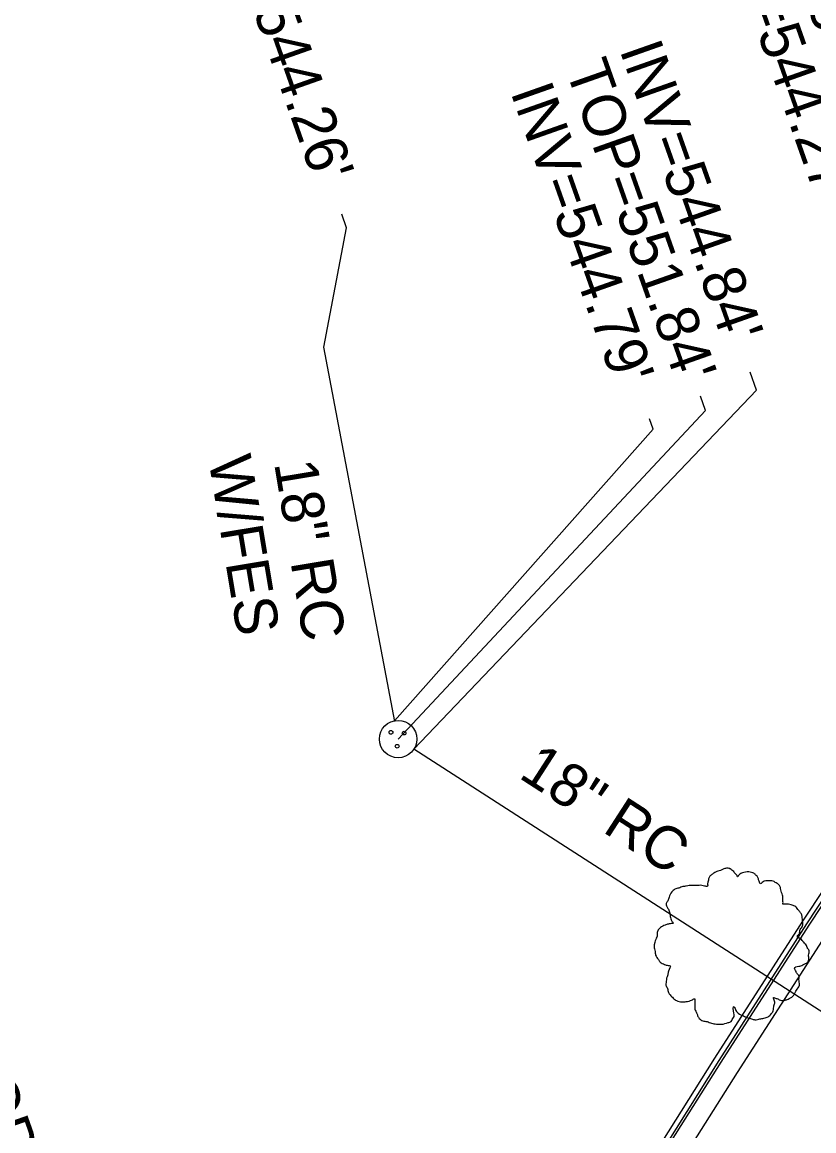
# Model space of a CAD drawing. Extents: x 2004847 to 2009016, y 1134161 to 1140101.
# Drawn here: x 2007863.9 to 2007937.9, y 1139162.8 to 1139266.5 of the extents above; entities that cross this region are included whole.
import ezdxf

# ---------------------------------------------------------------- set-up
doc = ezdxf.new("R2010")
doc.units = 0
for name, color, linetype in [('RD_EX_Curb', 7, 'Continuous'), ('RD_EX_DR_Inlet', 7, 'Continuous'), ('RD_EX_DR_Inlet_txCode', 7, 'Continuous'), ('RD_EX_DR_Pipe', 7, 'Continuous'), ('RD_EX_DR_Pipe_txCode', 7, 'Continuous'), ('RD_EX_Road', 7, 'Continuous'), ('RD_EX_VEG', 7, 'Continuous'), ('RD_Sketch2', 7, 'Continuous')]:
    doc.layers.add(name, color=color, linetype=linetype)

msp = doc.modelspace()

# ---------------------------------------------------------------- linework, layer by layer
at = {"layer": 'RD_EX_Curb'}
for points in [[(2007851.74, 1139039.76), (2007859.24, 1139052.98), (2007866.61, 1139066.11), (2007873.99, 1139079.28), (2007881.46, 1139092.4), (2007889.19, 1139105.44), (2007896.87, 1139118.33), (2007904.72, 1139131.27), (2007912.69, 1139144.1), (2007920.68, 1139156.93), (2007928.66, 1139169.64), (2007936.89, 1139182.44), (2007945.18, 1139194.94), (2007953.65, 1139207.52), (2007962.07, 1139219.98), (2007965.84, 1139225.5)], [(2007852.17, 1139039.53), (2007859.64, 1139052.76), (2007866.98, 1139065.9), (2007874.37, 1139079.07), (2007881.83, 1139092.18), (2007889.55, 1139105.22), (2007897.24, 1139118.11), (2007905.04, 1139131.08), (2007913.02, 1139143.89), (2007921.07, 1139156.68), (2007929.04, 1139169.4), (2007937.26, 1139182.2), (2007945.52, 1139194.72), (2007954.01, 1139207.28), (2007962.42, 1139219.75), (2007966.16, 1139225.27)], [(2007852.4, 1139039.41), (2007859.85, 1139052.64), (2007867.2, 1139065.77), (2007874.59, 1139078.94), (2007882.05, 1139092.06), (2007889.77, 1139105.09), (2007897.44, 1139117.99), (2007905.23, 1139130.96), (2007913.16, 1139143.81), (2007921.23, 1139156.58), (2007929.25, 1139169.27), (2007937.47, 1139182.06), (2007945.72, 1139194.58), (2007954.17, 1139207.17), (2007962.6, 1139219.62), (2007966.32, 1139225.16)]]:
    msp.add_lwpolyline(points, dxfattribs=at)
at = {"layer": 'RD_EX_DR_Inlet'}
for centre, radius in [((2007899.03, 1139199.47), 1.75), ((2007898.36, 1139200.1), 0.175), ((2007899.59, 1139200.03), 0.175), ((2007898.94, 1139198.8), 0.175)]:
    msp.add_circle(centre, radius, dxfattribs=at)
at = {"layer": 'RD_EX_DR_Inlet_txCode'}
for points in [[(2007892.07, 1139236.12), (2007894.21, 1139247.27), (2007893.76, 1139248.55)], [(2007900.5, 1139198.52), (2007932.53, 1139232.1), (2007931.94, 1139233.77)], [(2007899.03, 1139199.47), (2007927.78, 1139230.2), (2007927.3, 1139231.55)], [(2007898.7, 1139201.19), (2007922.88, 1139228.46), (2007922.54, 1139229.42)]]:
    msp.add_lwpolyline(points, dxfattribs=at)
at = {"layer": 'RD_EX_DR_Pipe'}
for p, q in [((2007898.72, 1139201.12), (2007892.07, 1139236.12)), ((2007976.72, 1139149.41), (2007900.5, 1139198.52))]:
    msp.add_line(p, q, dxfattribs=at)
at = {"layer": 'RD_EX_Road'}
msp.add_lwpolyline([(2007854.06, 1139038.51), (2007861.51, 1139051.72), (2007868.85, 1139064.84), (2007876.23, 1139078), (2007883.69, 1139091.1), (2007891.4, 1139104.12), (2007899.06, 1139117.02), (2007906.85, 1139129.97), (2007914.77, 1139142.81), (2007922.77, 1139155.61), (2007930.78, 1139168.29), (2007938.99, 1139181.07), (2007947.3, 1139193.55), (2007955.76, 1139206.1), (2007964.18, 1139218.54), (2007967.91, 1139224.07)], dxfattribs=at)
at = {"layer": 'RD_EX_VEG'}
for points in [[(2007930.04, 1139187.37), (2007929.74, 1139187.39), (2007929.42, 1139187.29), (2007929.17, 1139187.19), (2007928.94, 1139187.12), (2007928.72, 1139187.02), (2007928.42, 1139186.84), (2007928.19, 1139186.64), (2007928.07, 1139186.39), (2007928.02, 1139186.17), (2007927.97, 1139185.89), (2007927.97, 1139185.72), (2007927.84, 1139185.69), (2007927.69, 1139185.72), (2007927.44, 1139185.79), (2007927.19, 1139185.79), (2007926.94, 1139185.79), (2007926.59, 1139185.77), (2007926.25, 1139185.77), (2007925.97, 1139185.72), (2007925.65, 1139185.67), (2007925.27, 1139185.54), (2007924.92, 1139185.42), (2007924.62, 1139185.17), (2007924.37, 1139184.69), (2007924.25, 1139184.34), (2007924.1, 1139184.09), (2007924.25, 1139183.64), (2007924.42, 1139183.29), (2007924.45, 1139183.09), (2007924.52, 1139182.67), (2007924.62, 1139182.44), (2007924.75, 1139182.24), (2007924.67, 1139182.22), (2007924.3, 1139182.17), (2007924, 1139182.07), (2007923.57, 1139181.84), (2007923.35, 1139181.62), (2007923.25, 1139181.29), (2007923.22, 1139180.94), (2007923.12, 1139180.74), (2007923.05, 1139180.47), (2007923.02, 1139180.39), (2007922.97, 1139180.07), (2007923.07, 1139179.62), (2007923.1, 1139179.27), (2007923.22, 1139179.05), (2007923.37, 1139178.87), (2007923.55, 1139178.62), (2007923.95, 1139178.4), (2007924.27, 1139178.3), (2007924.47, 1139178.27), (2007924.3, 1139177.77), (2007924.25, 1139177.42), (2007924.12, 1139177.02), (2007924.12, 1139176.95), (2007924.07, 1139176.47), (2007924.22, 1139176.15), (2007924.3, 1139175.77), (2007924.47, 1139175.55), (2007924.75, 1139175.25), (2007925.07, 1139175.02), (2007925.57, 1139174.9), (2007925.97, 1139174.92), (2007926.55, 1139175.1), (2007926.79, 1139175.17), (2007926.77, 1139175), (2007926.79, 1139174.62), (2007926.79, 1139174.2), (2007926.94, 1139173.87), (2007927.04, 1139173.6), (2007927.19, 1139173.35), (2007927.52, 1139173.12), (2007927.92, 1139173.05), (2007928.34, 1139172.9), (2007928.79, 1139172.82), (2007929.29, 1139172.8), (2007929.89, 1139172.95), (2007930.17, 1139173.07), (2007930.27, 1139173.25), (2007930.47, 1139173.62), (2007930.42, 1139173.85), (2007930.44, 1139174.45), (2007930.54, 1139174.27), (2007930.72, 1139173.92), (2007931.22, 1139173.62), (2007931.62, 1139173.45), (2007932.09, 1139173.3), (2007932.39, 1139173.22), (2007932.87, 1139173.3), (2007933.24, 1139173.37), (2007933.62, 1139173.5), (2007933.92, 1139173.77), (2007934.09, 1139174.05), (2007934.14, 1139174.32), (2007934.22, 1139174.7), (2007934.27, 1139174.87)], [(2007934.27, 1139174.87), (2007934.19, 1139175.05), (2007934.14, 1139175.3), (2007934.22, 1139175.27), (2007934.39, 1139175.22), (2007934.67, 1139175.1), (2007934.89, 1139175.02), (2007935.22, 1139175.05), (2007935.49, 1139175.15), (2007935.94, 1139175.42), (2007936.22, 1139175.9), (2007936.49, 1139176.3), (2007936.57, 1139176.62), (2007936.52, 1139176.85), (2007936.49, 1139177.35), (2007936.29, 1139177.6), (2007936.24, 1139177.72), (2007936.14, 1139178.12), (2007936.22, 1139178.17), (2007936.49, 1139178.22), (2007936.87, 1139178.35), (2007937.14, 1139178.47), (2007937.37, 1139178.65), (2007937.44, 1139178.87), (2007937.42, 1139179.27), (2007937.47, 1139179.67), (2007937.39, 1139179.82), (2007937.29, 1139179.97), (2007937.22, 1139180.17), (2007937.07, 1139180.32), (2007936.97, 1139180.47), (2007936.87, 1139180.57), (2007936.74, 1139180.72), (2007936.57, 1139180.84), (2007936.42, 1139180.89), (2007936.37, 1139181.04), (2007936.52, 1139181.24), (2007936.57, 1139181.34), (2007936.59, 1139181.57), (2007936.82, 1139181.92), (2007936.87, 1139182.32), (2007936.82, 1139182.74), (2007936.77, 1139183.02), (2007936.62, 1139183.29), (2007936.42, 1139183.54), (2007936.29, 1139183.72), (2007936.12, 1139183.84), (2007935.79, 1139183.97), (2007935.54, 1139184.02), (2007935.19, 1139184.02), (2007934.99, 1139184.07), (2007935.02, 1139184.12), (2007935.02, 1139184.27), (2007935.02, 1139184.54), (2007934.94, 1139184.99), (2007934.79, 1139185.49), (2007934.79, 1139185.52), (2007934.69, 1139185.77), (2007934.47, 1139185.97), (2007934.29, 1139186.07), (2007934.09, 1139186.19), (2007933.84, 1139186.22), (2007933.54, 1139186.22), (2007933.27, 1139186.17), (2007933.07, 1139186.07), (2007932.89, 1139185.94), (2007932.82, 1139186.09), (2007932.72, 1139186.39), (2007932.67, 1139186.54), (2007932.52, 1139186.72), (2007932.29, 1139186.92), (2007931.84, 1139187.04), (2007931.22, 1139186.97), (2007930.92, 1139186.77), (2007930.77, 1139186.59), (2007930.72, 1139186.72), (2007930.52, 1139186.92), (2007930.42, 1139187.09), (2007930.24, 1139187.22), (2007930.09, 1139187.32), (2007929.99, 1139187.37)]]:
    msp.add_spline(points, degree=3, dxfattribs=at)

# ---------------------------------------------------------------- texts
at = {"layer": 'RD_EX_DR_Inlet_txCode'}
for s, p in [("INV=544.26'", (2007881.44, 1139278.95)), ("INV=544.84'", (2007919.71, 1139263.93)), ("TOP=551.84'", (2007914.65, 1139262.16)), ("INV=544.79'", (2007909.51, 1139259.99))]:
    msp.add_text(s, height=4, rotation=289.4494, dxfattribs=at).set_placement(p)
at = {"layer": 'RD_EX_DR_Pipe_txCode'}
for s, rotation, p in [('W/FES', 279.4046, (2007881.28, 1139225.65)), ('18" RC', 279.4046, (2007887.43, 1139225.27)), ('18" RC', 327.155, (2007910.19, 1139195.92))]:
    msp.add_text(s, height=4, rotation=rotation, dxfattribs=at).set_placement(p)
at = {"layer": 'RD_Sketch2'}
for s, p in [("TOP=554.09'", (2007932.55, 1139281.43)), ("INV=544.27'", (2007928.57, 1139276.92)), ("DROP IN=542.28'", (2007856.5, 1139174.56))]:
    msp.add_text(s, height=4, rotation=289.4494, dxfattribs=at).set_placement(p)

doc.saveas('drawing.dxf')
